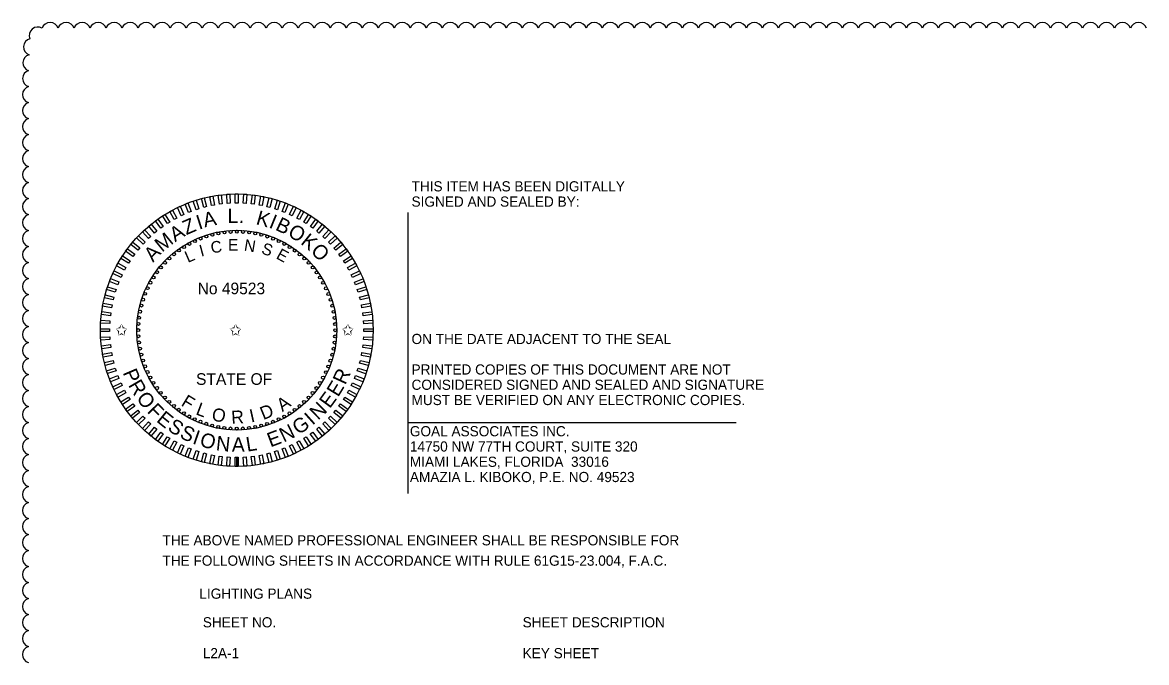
# Model space of a CAD drawing. Extents: x -811 to 10319, y -2309 to 9962.
# Drawn here: x -811.02 to -803.29, y -2303.15 to -2298.74 of the extents above; entities that cross this region are included whole.
import ezdxf

# ---------------------------------------------------------------- set-up
doc = ezdxf.new("R2010")
doc.units = 0
for name, color, linetype in [('AdhocPoint_dp', 7, 'Continuous'), ('PlotBorder_dp', 7, 'Continuous'), ('ScratchEle_dp', 7, 'Continuous'), ('TextMinor', 7, 'Continuous'), ('TextMisc', 7, 'Continuous'), ('TextShtNo', 7, 'Continuous')]:
    doc.layers.add(name, color=color, linetype=linetype)

msp = doc.modelspace()

# ---------------------------------------------------------------- linework, layer by layer
at = {"layer": 'AdhocPoint_dp'}
for p, q in [((-808.3678, -2300.0498), (-808.3678, -2301.9845)), ((-808.3678, -2301.4945), (-806.111, -2301.4945))]:
    msp.add_line(p, q, dxfattribs=at)
at = {"layer": 'ScratchEle_dp'}
for centre, start, end in [((-810.9126, -2298.8327), 57.90928, 202.90928), ((-810.8269, -2298.8012), 17.5, 162.5), ((-810.7168, -2298.8012), 17.5, 162.5), ((-810.6068, -2298.8012), 17.5, 162.5), ((-810.4968, -2298.8012), 17.5, 162.5), ((-810.3867, -2298.8012), 17.5, 162.5), ((-810.2767, -2298.8012), 17.5, 162.5), ((-810.1666, -2298.8012), 17.5, 162.5), ((-810.0566, -2298.8012), 17.5, 162.5), ((-809.9465, -2298.8012), 17.5, 162.5), ((-809.8365, -2298.8012), 17.5, 162.5), ((-809.7264, -2298.8012), 17.5, 162.5), ((-809.6164, -2298.8012), 17.5, 162.5), ((-809.5064, -2298.8012), 17.5, 162.5), ((-809.3963, -2298.8012), 17.5, 162.5), ((-809.2863, -2298.8012), 17.5, 162.5), ((-809.1762, -2298.8012), 17.5, 162.5), ((-809.0662, -2298.8012), 17.5, 162.5), ((-808.9561, -2298.8012), 17.5, 162.5), ((-808.8461, -2298.8012), 17.5, 162.5), ((-808.7361, -2298.8012), 17.5, 162.5), ((-808.626, -2298.8012), 17.5, 162.5), ((-808.516, -2298.8012), 17.5, 162.5), ((-808.4059, -2298.8012), 17.5, 162.5), ((-808.2959, -2298.8012), 17.5, 162.5), ((-808.1858, -2298.8012), 17.5, 162.5), ((-808.0758, -2298.8012), 17.5, 162.5), ((-807.9657, -2298.8012), 17.5, 162.5), ((-807.8557, -2298.8012), 17.5, 162.5), ((-807.7457, -2298.8012), 17.5, 162.5), ((-807.6356, -2298.8012), 17.5, 162.5), ((-807.5256, -2298.8012), 17.5, 162.5), ((-807.4155, -2298.8012), 17.5, 162.5), ((-807.3055, -2298.8012), 17.5, 162.5), ((-807.1954, -2298.8012), 17.5, 162.5), ((-807.0854, -2298.8012), 17.5, 162.5), ((-806.9754, -2298.8012), 17.5, 162.5), ((-806.8653, -2298.8012), 17.5, 162.5), ((-806.7553, -2298.8012), 17.5, 162.5), ((-806.6452, -2298.8012), 17.5, 162.5), ((-806.5352, -2298.8012), 17.5, 162.5), ((-806.4251, -2298.8012), 17.5, 162.5), ((-806.3151, -2298.8012), 17.5, 162.5), ((-806.205, -2298.8012), 17.5, 162.5), ((-806.095, -2298.8012), 17.5, 162.5), ((-805.985, -2298.8012), 17.5, 162.5), ((-805.8749, -2298.8012), 17.5, 162.5), ((-805.7649, -2298.8012), 17.5, 162.5), ((-805.6548, -2298.8012), 17.5, 162.5), ((-805.5448, -2298.8012), 17.5, 162.5), ((-805.4347, -2298.8012), 17.5, 162.5), ((-805.3247, -2298.8012), 17.5, 162.5), ((-805.2147, -2298.8012), 17.5, 162.5), ((-805.1046, -2298.8012), 17.5, 162.5), ((-804.9946, -2298.8012), 17.5, 162.5), ((-804.8845, -2298.8012), 17.5, 162.5), ((-804.7745, -2298.8012), 17.5, 162.5), ((-804.6644, -2298.8012), 17.5, 162.5), ((-804.5544, -2298.8012), 17.5, 162.5), ((-804.4443, -2298.8012), 17.5, 162.5), ((-804.3343, -2298.8012), 17.5, 162.5), ((-804.2243, -2298.8012), 17.5, 162.5), ((-804.1142, -2298.8012), 17.5, 162.5), ((-804.0042, -2298.8012), 17.5, 162.5), ((-803.8941, -2298.8012), 17.5, 162.5), ((-803.7841, -2298.8012), 17.5, 162.5), ((-803.674, -2298.8012), 17.5, 162.5), ((-803.564, -2298.8012), 17.5, 162.5), ((-803.4539, -2298.8012), 17.5, 162.5), ((-803.3439, -2298.8012), 17.5, 162.5), ((-810.9514, -2298.9111), 104.30482, 249.30482), ((-810.9558, -2299.0205), 106.11208, 251.11208), ((-810.9578, -2299.1303), 106.82878, 251.82878), ((-810.9587, -2299.2402), 107.24432, 252.24432), ((-810.9589, -2299.3502), 107.48117, 252.48117), ((-810.959, -2299.4602), 107.5, 252.5), ((-810.959, -2299.5703), 107.5, 252.5), ((-810.959, -2299.6803), 107.5, 252.5), ((-810.959, -2299.7904), 107.5, 252.5), ((-810.959, -2299.9004), 107.5, 252.5), ((-810.959, -2300.0104), 107.5, 252.5), ((-810.959, -2300.1205), 107.5, 252.5), ((-810.959, -2300.2305), 107.5, 252.5), ((-810.959, -2300.3406), 107.5, 252.5), ((-810.959, -2300.4506), 107.5, 252.5), ((-810.959, -2300.5607), 107.5, 252.5), ((-810.959, -2300.6707), 107.5, 252.5), ((-810.959, -2300.7807), 107.5, 252.5), ((-810.959, -2300.8908), 107.5, 252.5), ((-810.959, -2301.0008), 107.5, 252.5), ((-810.959, -2301.1109), 107.5, 252.5), ((-810.959, -2301.2209), 107.5, 252.5), ((-810.959, -2301.331), 107.5, 252.5), ((-810.959, -2301.441), 107.5, 252.5), ((-810.959, -2301.5511), 107.5, 252.5), ((-810.959, -2301.6611), 107.5, 252.5), ((-810.959, -2301.7711), 107.5, 252.5), ((-810.959, -2301.8812), 107.5, 252.5), ((-810.959, -2301.9912), 107.5, 252.5), ((-810.959, -2302.1013), 107.5, 252.5), ((-810.959, -2302.2113), 107.5, 252.5), ((-810.959, -2302.3214), 107.5, 252.5), ((-810.959, -2302.4314), 107.5, 252.5), ((-810.959, -2302.5414), 107.5, 252.5), ((-810.959, -2302.6515), 107.5, 252.5), ((-810.959, -2302.7615), 107.5, 252.5), ((-810.959, -2302.8716), 107.5, 252.5), ((-810.959, -2302.9816), 107.5, 252.5), ((-810.959, -2303.0917), 107.5, 252.5)]:
    msp.add_arc(centre, 0.0577, start, end, dxfattribs=at)
at = {"layer": 'TextMinor'}
for radius in [0.9371, 0.6872]:
    msp.add_circle((-809.5436, -2300.8604), radius, dxfattribs=at)
at = {"layer": 'TextShtNo'}
for p, q in [((-809.5535, -2301.7975), (-809.5537, -2301.735)), ((-809.5436, -2301.7975), (-809.5437, -2301.735)), ((-809.5336, -2301.7975), (-809.5337, -2301.735))]:
    msp.add_line(p, q, dxfattribs=at)
for points in [[(-809.6974, -2299.9993), (-809.7173, -2300.0031), (-809.729, -2299.9417), (-809.7091, -2299.938)], [(-809.6431, -2299.9913), (-809.6631, -2299.9938), (-809.6709, -2299.9319), (-809.6509, -2299.9294)], [(-809.5883, -2299.9868), (-809.6084, -2299.988), (-809.6124, -2299.9257), (-809.5922, -2299.9245)], [(-809.5334, -2299.9857), (-809.5535, -2299.9857), (-809.5535, -2299.9233), (-809.5334, -2299.9233)], [(-809.4785, -2299.9881), (-809.4986, -2299.9868), (-809.4947, -2299.9245), (-809.4745, -2299.9258)], [(-809.4238, -2299.9939), (-809.4438, -2299.9913), (-809.436, -2299.9294), (-809.416, -2299.9319)], [(-809.3697, -2300.0031), (-809.3895, -2299.9993), (-809.3778, -2299.938), (-809.358, -2299.9418)], [(-809.9068, -2300.0646), (-809.925, -2300.0732), (-809.9516, -2300.0167), (-809.9333, -2300.0081)], [(-809.8561, -2300.0434), (-809.8748, -2300.0508), (-809.8978, -2299.9928), (-809.8791, -2299.9853)], [(-809.8042, -2300.0254), (-809.8233, -2300.0316), (-809.8426, -2299.9722), (-809.8234, -2299.966)], [(-809.7512, -2300.0106), (-809.7708, -2300.0157), (-809.7863, -2299.9552), (-809.7667, -2299.9502)], [(-809.3162, -2300.0157), (-809.3357, -2300.0107), (-809.3202, -2299.9502), (-809.3006, -2299.9552)], [(-809.2636, -2300.0316), (-809.2828, -2300.0254), (-809.2635, -2299.966), (-809.2443, -2299.9723)], [(-809.2121, -2300.0509), (-809.2309, -2300.0434), (-809.2079, -2299.9854), (-809.1891, -2299.9928)], [(-809.1619, -2300.0733), (-809.1802, -2300.0647), (-809.1536, -2300.0082), (-809.1353, -2300.0168)], [(-810.0036, -2300.1164), (-810.0207, -2300.1272), (-810.0541, -2300.0745), (-810.0371, -2300.0637)], [(-809.956, -2300.089), (-809.9737, -2300.0987), (-810.0038, -2300.044), (-809.9861, -2300.0343)], [(-809.1132, -2300.0988), (-809.1309, -2300.0891), (-809.1009, -2300.0344), (-809.0832, -2300.0441)], [(-809.0663, -2300.1273), (-809.0833, -2300.1165), (-809.0499, -2300.0638), (-809.0328, -2300.0746)], [(-810.1349, -2300.2158), (-810.1496, -2300.2296), (-810.1923, -2300.1841), (-810.1776, -2300.1703)], [(-810.0932, -2300.1799), (-810.1088, -2300.1928), (-810.1486, -2300.1447), (-810.133, -2300.1318)], [(-810.0494, -2300.1468), (-810.0658, -2300.1586), (-810.1024, -2300.1081), (-810.0861, -2300.0963)], [(-809.0212, -2300.1587), (-809.0375, -2300.1469), (-809.0008, -2300.0964), (-808.9845, -2300.1082)], [(-808.9782, -2300.1929), (-808.9937, -2300.18), (-808.9539, -2300.132), (-808.9384, -2300.1448)], [(-808.9374, -2300.2297), (-808.9521, -2300.2159), (-808.9094, -2300.1704), (-808.8946, -2300.1842)], [(-810.1742, -2300.2542), (-810.188, -2300.2689), (-810.2335, -2300.2262), (-810.2197, -2300.2115)], [(-808.899, -2300.269), (-808.9128, -2300.2543), (-808.8673, -2300.2116), (-808.8535, -2300.2263)], [(-810.2452, -2300.338), (-810.2571, -2300.3543), (-810.3076, -2300.3176), (-810.2957, -2300.3013)], [(-810.211, -2300.295), (-810.2239, -2300.3105), (-810.272, -2300.2707), (-810.2591, -2300.2552)], [(-808.8631, -2300.3107), (-808.876, -2300.2951), (-808.8279, -2300.2553), (-808.815, -2300.2709)], [(-808.8299, -2300.3545), (-808.8418, -2300.3382), (-808.7913, -2300.3015), (-808.7794, -2300.3178)], [(-810.3051, -2300.4301), (-810.3149, -2300.4477), (-810.3696, -2300.4177), (-810.3598, -2300.4)], [(-810.2766, -2300.3831), (-810.2874, -2300.4001), (-810.3401, -2300.3667), (-810.3293, -2300.3496)], [(-808.7996, -2300.4003), (-808.8104, -2300.3833), (-808.7577, -2300.3498), (-808.7469, -2300.3668)], [(-808.7722, -2300.4479), (-808.7819, -2300.4302), (-808.7272, -2300.4002), (-808.7175, -2300.4178)], [(-810.3307, -2300.4787), (-810.3392, -2300.497), (-810.3957, -2300.4704), (-810.3871, -2300.4522)], [(-808.7478, -2300.4972), (-808.7564, -2300.4789), (-808.6999, -2300.4523), (-808.6913, -2300.4706)], [(-810.3531, -2300.5289), (-810.3605, -2300.5477), (-810.4185, -2300.5247), (-810.4111, -2300.5059)], [(-808.7265, -2300.5478), (-808.734, -2300.5291), (-808.6759, -2300.5061), (-808.6685, -2300.5249)], [(-810.3882, -2300.633), (-810.3932, -2300.6525), (-810.4537, -2300.637), (-810.4487, -2300.6175)], [(-810.3723, -2300.5804), (-810.3785, -2300.5996), (-810.4379, -2300.5803), (-810.4316, -2300.5611)], [(-808.7085, -2300.5998), (-808.7148, -2300.5806), (-808.6554, -2300.5613), (-808.6492, -2300.5805)], [(-808.6938, -2300.6527), (-808.6988, -2300.6332), (-808.6384, -2300.6176), (-808.6334, -2300.6372)], [(-810.4008, -2300.6865), (-810.4046, -2300.7063), (-810.4659, -2300.6946), (-810.4621, -2300.6748)], [(-808.6825, -2300.7065), (-808.6862, -2300.6866), (-808.6249, -2300.675), (-808.6211, -2300.6948)], [(-810.4101, -2300.7406), (-810.4126, -2300.7607), (-810.4745, -2300.7528), (-810.472, -2300.7328)], [(-808.6745, -2300.7608), (-808.677, -2300.7408), (-808.6151, -2300.733), (-808.6126, -2300.753)], [(-810.4182, -2300.8502), (-810.4182, -2300.8704), (-810.4806, -2300.8704), (-810.4806, -2300.8502)], [(-810.4159, -2300.7953), (-810.4171, -2300.8154), (-810.4794, -2300.8115), (-810.4782, -2300.7914)], [(-808.67, -2300.8156), (-808.6712, -2300.7955), (-808.6089, -2300.7916), (-808.6077, -2300.8117)], [(-808.6689, -2300.8705), (-808.6689, -2300.8504), (-808.6065, -2300.8504), (-808.6065, -2300.8705)], [(-810.4171, -2300.9051), (-810.4159, -2300.9253), (-810.4782, -2300.9292), (-810.4794, -2300.909)], [(-808.6712, -2300.9255), (-808.67, -2300.9053), (-808.6077, -2300.9092), (-808.6089, -2300.9294)], [(-810.4126, -2300.9599), (-810.4101, -2300.9799), (-810.472, -2300.9877), (-810.4745, -2300.9677)], [(-810.4046, -2301.0143), (-810.4009, -2301.0341), (-810.4622, -2301.0458), (-810.466, -2301.026)], [(-808.6863, -2301.0343), (-808.6825, -2301.0144), (-808.6212, -2301.0261), (-808.625, -2301.046)], [(-808.677, -2300.9801), (-808.6745, -2300.9601), (-808.6126, -2300.9679), (-808.6151, -2300.9879)], [(-810.3933, -2301.068), (-810.3883, -2301.0876), (-810.4487, -2301.1031), (-810.4537, -2301.0836)], [(-808.6989, -2301.0878), (-808.6939, -2301.0682), (-808.6334, -2301.0837), (-808.6384, -2301.1033)], [(-810.3786, -2301.121), (-810.3723, -2301.1402), (-810.4317, -2301.1595), (-810.4379, -2301.1403)], [(-810.3606, -2301.1729), (-810.3531, -2301.1917), (-810.4112, -2301.2146), (-810.4186, -2301.1959)], [(-808.734, -2301.1918), (-808.7266, -2301.1731), (-808.6686, -2301.196), (-808.676, -2301.2148)], [(-808.7148, -2301.1403), (-808.7086, -2301.1212), (-808.6492, -2301.1404), (-808.6555, -2301.1596)], [(-810.3393, -2301.2236), (-810.3307, -2301.2418), (-810.3872, -2301.2684), (-810.3958, -2301.2501)], [(-808.7565, -2301.242), (-808.7479, -2301.2237), (-808.6914, -2301.2503), (-808.7, -2301.2686)], [(-810.3149, -2301.2728), (-810.3052, -2301.2905), (-810.3599, -2301.3206), (-810.3696, -2301.3029)], [(-810.2875, -2301.3204), (-810.2767, -2301.3375), (-810.3294, -2301.3709), (-810.3402, -2301.3539)], [(-808.8105, -2301.3376), (-808.7997, -2301.3206), (-808.747, -2301.354), (-808.7578, -2301.3711)], [(-808.782, -2301.2907), (-808.7722, -2301.273), (-808.7176, -2301.3031), (-808.7273, -2301.3207)], [(-810.2572, -2301.3663), (-810.2453, -2301.3826), (-810.2958, -2301.4193), (-810.3077, -2301.4029)], [(-808.8419, -2301.3827), (-808.83, -2301.3664), (-808.7796, -2301.4031), (-808.7914, -2301.4194)], [(-810.224, -2301.4101), (-810.2111, -2301.4256), (-810.2592, -2301.4654), (-810.2721, -2301.4498)], [(-810.1881, -2301.4517), (-810.1743, -2301.4664), (-810.2198, -2301.5091), (-810.2336, -2301.4944)], [(-808.9129, -2301.4665), (-808.8991, -2301.4518), (-808.8536, -2301.4946), (-808.8674, -2301.5093)], [(-808.8761, -2301.4258), (-808.8632, -2301.4102), (-808.8151, -2301.45), (-808.828, -2301.4655)], [(-810.1497, -2301.491), (-810.135, -2301.5048), (-810.1778, -2301.5503), (-810.1925, -2301.5365)], [(-810.1089, -2301.5278), (-810.0934, -2301.5407), (-810.1332, -2301.5888), (-810.1487, -2301.5759)], [(-810.0659, -2301.562), (-810.0496, -2301.5739), (-810.0863, -2301.6244), (-810.1026, -2301.6125)], [(-809.0377, -2301.574), (-809.0213, -2301.5621), (-808.9847, -2301.6126), (-809.001, -2301.6245)], [(-808.9939, -2301.5408), (-808.9783, -2301.5279), (-808.9385, -2301.576), (-808.9541, -2301.5889)], [(-808.9522, -2301.505), (-808.9375, -2301.4911), (-808.8948, -2301.5366), (-808.9095, -2301.5505)], [(-810.0208, -2301.5934), (-810.0038, -2301.6042), (-810.0372, -2301.6569), (-810.0543, -2301.6461)], [(-809.9739, -2301.6219), (-809.9562, -2301.6317), (-809.9862, -2301.6864), (-810.0039, -2301.6766)], [(-809.1311, -2301.6318), (-809.1134, -2301.622), (-809.0833, -2301.6767), (-809.101, -2301.6865)], [(-809.0835, -2301.6043), (-809.0664, -2301.5935), (-809.033, -2301.6462), (-809.05, -2301.657)], [(-809.9252, -2301.6475), (-809.9069, -2301.6561), (-809.9335, -2301.7125), (-809.9518, -2301.7039)], [(-809.875, -2301.6699), (-809.8562, -2301.6773), (-809.8792, -2301.7353), (-809.898, -2301.7279)], [(-809.8235, -2301.6891), (-809.8043, -2301.6953), (-809.8236, -2301.7547), (-809.8428, -2301.7485)], [(-809.7709, -2301.705), (-809.7514, -2301.7101), (-809.7669, -2301.7705), (-809.7865, -2301.7655)], [(-809.3359, -2301.7101), (-809.3163, -2301.7051), (-809.3008, -2301.7655), (-809.3204, -2301.7706)], [(-809.2829, -2301.6954), (-809.2638, -2301.6891), (-809.2445, -2301.7485), (-809.2637, -2301.7547)], [(-809.231, -2301.6774), (-809.2123, -2301.6699), (-809.1893, -2301.728), (-809.2081, -2301.7354)], [(-809.1803, -2301.6561), (-809.1621, -2301.6475), (-809.1355, -2301.704), (-809.1538, -2301.7126)], [(-809.7175, -2301.7176), (-809.6976, -2301.7214), (-809.7093, -2301.7827), (-809.7291, -2301.779)], [(-809.6633, -2301.7269), (-809.6433, -2301.7294), (-809.6511, -2301.7913), (-809.6711, -2301.7888)], [(-809.6086, -2301.7327), (-809.5885, -2301.7339), (-809.5924, -2301.7962), (-809.6126, -2301.795)], [(-809.5537, -2301.735), (-809.5336, -2301.735), (-809.5336, -2301.7975), (-809.5537, -2301.7975)], [(-809.4988, -2301.734), (-809.4787, -2301.7327), (-809.4747, -2301.795), (-809.4949, -2301.7963)], [(-809.444, -2301.7294), (-809.424, -2301.7269), (-809.4162, -2301.7888), (-809.4362, -2301.7913)], [(-809.3897, -2301.7215), (-809.3698, -2301.7177), (-809.3581, -2301.779), (-809.378, -2301.7828)]]:
    msp.add_lwpolyline(points, close=True, dxfattribs=at)
for centre in [(-809.8314, -2300.2474), (-809.7923, -2300.2305), (-809.7523, -2300.2161), (-809.7114, -2300.2043), (-809.6699, -2300.1951), (-809.6279, -2300.1884), (-809.5855, -2300.1845), (-809.543, -2300.1832), (-809.5005, -2300.1845), (-809.4581, -2300.1886), (-809.4161, -2300.1953), (-809.3746, -2300.2046), (-809.3338, -2300.2165), (-809.2937, -2300.2309), (-809.2547, -2300.2479), (-809.9411, -2300.3122), (-809.9059, -2300.2883), (-809.8693, -2300.2667), (-809.2168, -2300.2672), (-809.1802, -2300.2889), (-809.145, -2300.3128), (-810.0368, -2300.3964), (-810.0067, -2300.3663), (-809.9748, -2300.3382), (-809.1115, -2300.3389), (-809.0796, -2300.3671), (-809.0495, -2300.3972), (-810.0911, -2300.4619), (-810.065, -2300.4283), (-809.0214, -2300.4291), (-808.9954, -2300.4628), (-810.1367, -2300.5336), (-810.115, -2300.497), (-808.9715, -2300.498), (-808.9498, -2300.5346), (-810.173, -2300.6105), (-810.1561, -2300.5715), (-808.9306, -2300.5725), (-808.9137, -2300.6116), (-810.1993, -2300.6914), (-810.1874, -2300.6506), (-808.8993, -2300.6516), (-808.8875, -2300.6925), (-810.2153, -2300.7749), (-810.2086, -2300.7329), (-808.8782, -2300.734), (-808.8716, -2300.7761), (-810.2207, -2300.8598), (-810.2194, -2300.8173), (-808.8677, -2300.8184), (-808.8664, -2300.8609), (-810.2194, -2300.9023), (-810.2155, -2300.9447), (-808.8718, -2300.9458), (-808.8677, -2300.9035), (-810.2089, -2300.9867), (-810.1996, -2301.0282), (-808.8878, -2301.0293), (-808.8785, -2300.9878), (-810.1878, -2301.0691), (-808.8997, -2301.0702), (-810.1734, -2301.1091), (-810.1565, -2301.1482), (-810.1373, -2301.1861), (-808.931, -2301.1492), (-808.9141, -2301.1102), (-810.1156, -2301.2228), (-810.0917, -2301.258), (-808.996, -2301.2589), (-808.9721, -2301.2237), (-808.9504, -2301.1871), (-810.0657, -2301.2916), (-810.0376, -2301.3235), (-809.0503, -2301.3244), (-809.0221, -2301.2925), (-810.0075, -2301.3536), (-809.9756, -2301.3818), (-809.9421, -2301.4079), (-809.146, -2301.4086), (-809.1123, -2301.3825), (-809.0804, -2301.3544), (-809.9069, -2301.4318), (-809.8703, -2301.4535), (-809.8324, -2301.4729), (-809.7934, -2301.4898), (-809.2948, -2301.4902), (-809.2557, -2301.4734), (-809.2178, -2301.4541), (-809.1812, -2301.4324), (-809.7534, -2301.5042), (-809.7125, -2301.5161), (-809.671, -2301.5255), (-809.629, -2301.5322), (-809.5866, -2301.5362), (-809.5436, -2301.5376), (-809.5016, -2301.5363), (-809.4592, -2301.5323), (-809.4172, -2301.5257), (-809.3757, -2301.5164), (-809.3348, -2301.5046)]:
    msp.add_circle(centre, 0.01, dxfattribs=at)

# ---------------------------------------------------------------- texts
at = {"layer": 'PlotBorder_dp'}
for s, height, p in [('THIS ITEM HAS BEEN DIGITALLY', 0.07, (-808.3418, -2299.9057)), ('SIGNED AND SEALED BY:', 0.07, (-808.3418, -2300.0107)), ('No 49523', 0.07997, (-809.8124, -2300.6132)), ('ON THE DATE ADJACENT TO THE SEAL', 0.07, (-808.3418, -2300.9557)), ('PRINTED COPIES OF THIS DOCUMENT ARE NOT ', 0.07, (-808.3418, -2301.1657)), ('STATE OF', 0.07997, (-809.8232, -2301.2364)), ('CONSIDERED SIGNED AND SEALED AND SIGNATURE ', 0.07, (-808.3418, -2301.2707)), ('MUST BE VERIFIED ON ANY ELECTRONIC COPIES.', 0.07, (-808.3418, -2301.3757)), ('GOAL ASSOCIATES INC.', 0.07, (-808.3533, -2301.5904)), ('14750 NW 77TH COURT, SUITE 320', 0.07, (-808.3533, -2301.6954)), ('MIAMI LAKES, FLORIDA  33016', 0.07, (-808.3533, -2301.8004)), ('AMAZIA L. KIBOKO, P.E. NO. 49523', 0.07, (-808.3533, -2301.9054)), ('THE ABOVE NAMED PROFESSIONAL ENGINEER SHALL BE RESPONSIBLE FOR ', 0.07, (-810.0542, -2302.3408)), ('THE FOLLOWING SHEETS IN ACCORDANCE WITH RULE 61G15-23.004, F.A.C.', 0.07, (-810.0542, -2302.4808)), ('LIGHTING PLANS', 0.07, (-809.8005, -2302.7079))]:
    msp.add_text(s, height=height, dxfattribs=at).set_placement(p)
for s, height, rotation, p in [('Z', 0.1, 23.30524, (-809.8904, -2300.2073)), ('I', 0.1, 17.68363, (-809.8035, -2300.1697)), ('A', 0.1, 11.91844, (-809.7642, -2300.1537)), ('L', 0.1, 359.96623, (-809.6071, -2300.1234)), ('K', 0.1, 344.27273, (-809.4165, -2300.1305)), ('I', 0.1, 337.77772, (-809.328, -2300.1524)), ('B', 0.1, 334.48695, (-809.284, -2300.1677)), ('A', 0.1, 31.46601, (-809.9677, -2300.2559)), ('.', 0.1, 353.78581, (-809.5305, -2300.1205)), ('O', 0.1, 327.82385, (-809.1994, -2300.2063)), ('M', 0.1, 39.30005, (-810.0568, -2300.328)), ('K', 0.1, 321.0594, (-809.1098, -2300.2634)), ('A', 0.1, 46.80938, (-810.119, -2300.3964)), ('O', 0.1, 314.20329, (-809.0402, -2300.321)), ('P', 0.1, 293.19548, (-810.3289, -2301.1518)), ('R', 0.1, 65.28865, (-808.7975, -2301.2412)), ('R', 0.1, 300.25949, (-810.2921, -2301.2377)), ('E', 0.1, 58.61694, (-808.8467, -2301.3251)), ('O', 0.1, 307.26617, (-810.2379, -2301.3295)), ('F', 0.09, 328.53399, (-809.9318, -2301.3755)), ('A', 0.09, 35.54629, (-809.2293, -2301.4248)), ('E', 0.1, 53.99864, (-808.9039, -2301.4038)), ('F', 0.1, 314.20329, (-810.1645, -2301.4219)), ('L', 0.09, 339.48752, (-809.8307, -2301.4384)), ('O', 0.09, 348.08156, (-809.7212, -2301.479)), ('I', 0.09, 12.52485, (-809.445, -2301.4961)), ('D', 0.09, 22.22228, (-809.3609, -2301.4792)), ('N', 0.1, 44.34211, (-808.9839, -2301.4836)), ('E', 0.1, 321.0594, (-810.1012, -2301.4855)), ('S', 0.1, 327.82385, (-810.025, -2301.546)), ('R', 0.09, 3.10738, (-809.5792, -2301.5052)), ('G', 0.1, 34.11362, (-809.1193, -2301.5838)), ('I', 0.1, 41.83906, (-809.0232, -2301.5178)), ('S', 0.1, 334.48695, (-809.942, -2301.5974)), ('I', 0.1, 341.03996, (-809.8534, -2301.6387)), ('E', 0.1, 20.51248, (-809.312, -2301.6672)), ('N', 0.1, 26.0618, (-809.2205, -2301.6339)), ('O', 0.1, 344.27273, (-809.8043, -2301.6562)), ('N', 0.1, 353.78581, (-809.6899, -2301.6862)), ('A', 0.1, 359.96623, (-809.5777, -2301.6971)), ('L', 0.1, 8.98261, (-809.4721, -2301.6963))]:
    msp.add_text(s, height=height, rotation=rotation, dxfattribs=at).set_placement(p)
at = {"layer": 'TextMisc'}
for s, p in [('SHEET NO.', (-809.777, -2302.9048)), ('SHEET DESCRIPTION', (-807.5781, -2302.9048)), ('L2A-1', (-809.777, -2303.117)), ('KEY SHEET', (-807.5781, -2303.117))]:
    msp.add_text(s, height=0.07, dxfattribs=at).set_placement(p)
at = {"layer": 'TextShtNo'}
for s, rotation, p in [('C', 8.98261, (-809.7165, -2300.3327)), ('E', 359.96623, (-809.6038, -2300.3138)), ('N', 350.64643, (-809.497, -2300.3124)), ('L', 23.30524, (-809.8796, -2300.3982)), ('I', 14.81888, (-809.789, -2300.3554)), ('S', 341.03996, (-809.3799, -2300.3312)), ('E', 331.16864, (-809.2785, -2300.3637))]:
    msp.add_text(s, height=0.08, rotation=rotation, dxfattribs=at).set_placement(p)
for p in [(-810.3782, -2300.8983), (-809.5938, -2300.8983), (-808.8223, -2300.8983)]:
    msp.add_text('✩', height=0.08, dxfattribs=at).set_placement(p)

doc.saveas('drawing.dxf')
